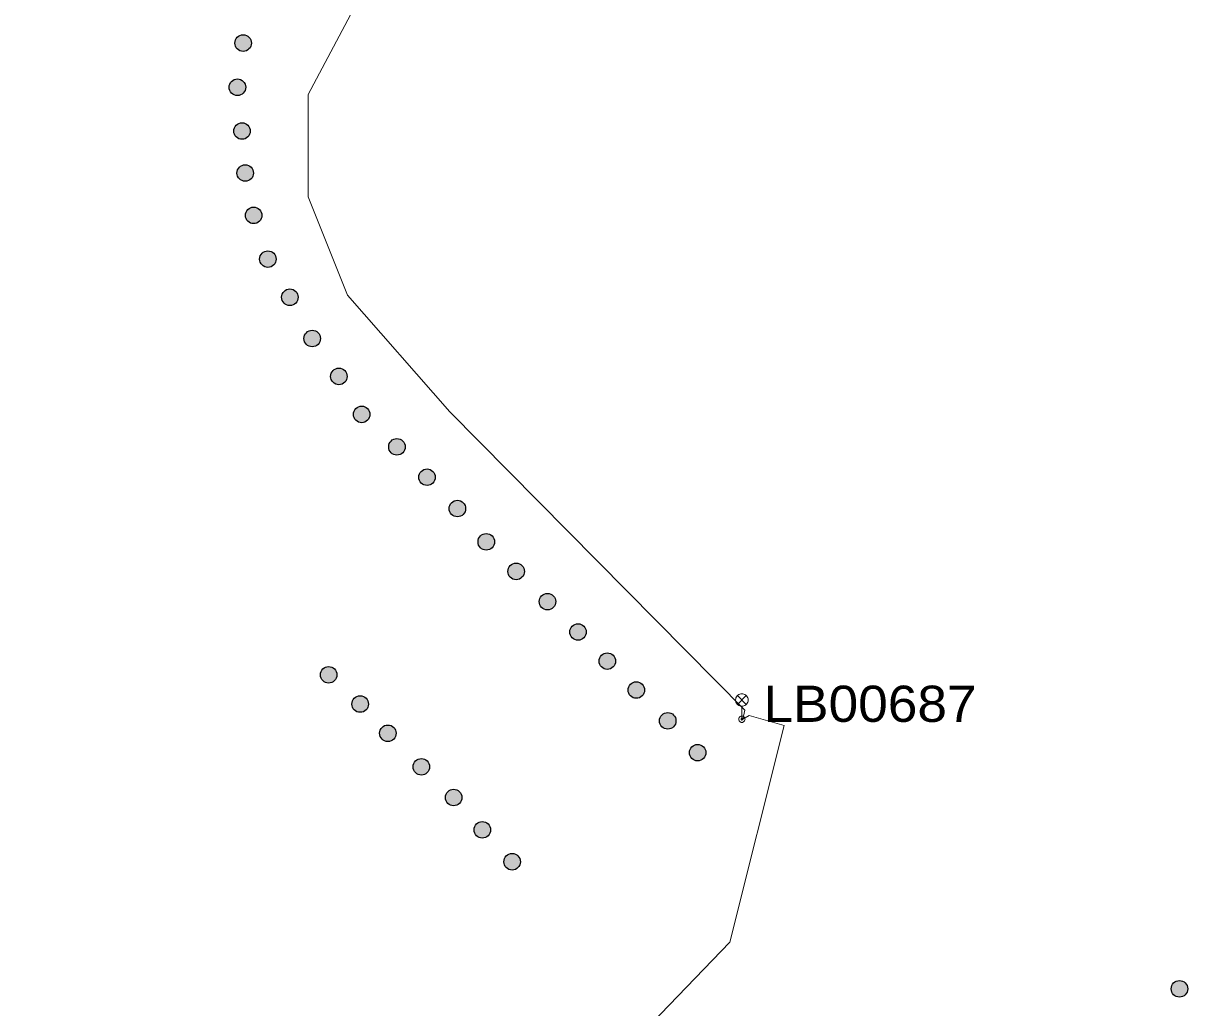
# Model space of a CAD drawing. Extents: x -688049 to -687261, y -973611 to -973038.
# Drawn here: x -687678.7 to -687609, y -973383.4 to -973324.5 of the extents above; entities that cross this region are included whole.
import ezdxf

# ---------------------------------------------------------------- set-up
doc = ezdxf.new("R2010")
doc.units = 0
doc.header["$LTSCALE"] = 0.87
doc.layers.add('1', color=7, linetype='Continuous', lineweight=13)

msp = doc.modelspace()

# ---------------------------------------------------------------- hatches: boundary and pattern name
at = {"layer": '1'}
for points in [[(-687665.392, -973326.145, 1), (-687665.691, -973325.201, 1)], [(-687665.735, -973328.789, 1), (-687666.034, -973327.845, 1)], [(-687665.46, -973331.41, 1), (-687665.759, -973330.466, 1)], [(-687665.267, -973333.924, 1), (-687665.566, -973332.979, 1)], [(-687664.763, -973336.457, 1), (-687665.062, -973335.513, 1)], [(-687663.91, -973339.074, 1), (-687664.209, -973338.13, 1)], [(-687662.593, -973341.358, 1), (-687662.892, -973340.414, 1)], [(-687661.255, -973343.827, 1), (-687661.553, -973342.883, 1)], [(-687659.656, -973346.096, 1), (-687659.955, -973345.152, 1)], [(-687658.292, -973348.37, 1), (-687658.591, -973347.426, 1)], [(-687656.18, -973350.311, 1), (-687656.478, -973349.367, 1)], [(-687654.379, -973352.128, 1), (-687654.678, -973351.184, 1)], [(-687652.558, -973354.004, 1), (-687652.857, -973353.059, 1)], [(-687650.829, -973355.995, 1), (-687651.128, -973355.051, 1)], [(-687649.04, -973357.767, 1), (-687649.338, -973356.823, 1)], [(-687647.162, -973359.575, 1), (-687647.461, -973358.631, 1)], [(-687645.333, -973361.392, 1), (-687645.632, -973360.448, 1)], [(-687643.58, -973363.135, 1), (-687643.878, -973362.191, 1)], [(-687660.271, -973363.955, 1), (-687660.57, -973363.011, 1)], [(-687641.841, -973364.867, 1), (-687642.14, -973363.923, 1)], [(-687658.383, -973365.705, 1), (-687658.682, -973364.761, 1)], [(-687639.961, -973366.71, 1), (-687640.26, -973365.766, 1)], [(-687656.723, -973367.454, 1), (-687657.022, -973366.51, 1)], [(-687638.17, -973368.613, 1), (-687638.469, -973367.669, 1)], [(-687654.717, -973369.461, 1), (-687655.016, -973368.517, 1)], [(-687652.784, -973371.299, 1), (-687653.083, -973370.355, 1)], [(-687651.068, -973373.233, 1), (-687651.367, -973372.289, 1)], [(-687649.28, -973375.143, 1), (-687649.578, -973374.199, 1)], [(-687609.311, -973382.749, 1), (-687609.609, -973381.805, 1)]]:
    msp.add_hatch(color=256, dxfattribs=at).paths.add_polyline_path(points)

# ---------------------------------------------------------------- linework, layer by layer
for p, q in [((-687635.935, -973364.725), (-687635.405, -973365.255)), ((-687635.935, -973365.255), (-687635.405, -973364.725)), ((-687635.67, -973366.14), (-687635.67, -973365.365))]:
    msp.add_line(p, q, dxfattribs=at)
for points in [[(-687678.71, -973323.61), (-687678.206, -973323.669), (-687658.771, -973323.345), (-687661.643, -973328.751), (-687661.643, -973334.873), (-687659.29, -973340.758), (-687653.159, -973347.738), (-687635.491, -973365.599), (-687635.62, -973366.14)], [(-687635.62, -973366.14), (-687635.225, -973365.919), (-687633.134, -973366.526), (-687636.395, -973379.478), (-687647.285, -973390.792), (-687642.829, -973395.545), (-687642.829, -973396.299), (-687642.074, -973396.299), (-687632.804, -973405.662), (-687632.954, -973409.811), (-687635.757, -973411.904), (-687636.24, -973411.98)]]:
    msp.add_lwpolyline(points, dxfattribs=at)
for points in [[(-687635.295, -973364.99), (-687635.301, -973364.925), (-687635.318, -973364.862), (-687635.345, -973364.802), (-687635.383, -973364.749), (-687635.429, -973364.703), (-687635.482, -973364.665), (-687635.542, -973364.638), (-687635.605, -973364.621), (-687635.67, -973364.615), (-687635.735, -973364.621), (-687635.798, -973364.638), (-687635.858, -973364.665), (-687635.911, -973364.703), (-687635.957, -973364.749), (-687635.995, -973364.802), (-687636.022, -973364.862), (-687636.039, -973364.925), (-687636.045, -973364.99), (-687636.039, -973365.055), (-687636.022, -973365.118), (-687635.995, -973365.178), (-687635.957, -973365.231), (-687635.911, -973365.277), (-687635.858, -973365.315), (-687635.798, -973365.342), (-687635.735, -973365.359), (-687635.67, -973365.365), (-687635.605, -973365.359), (-687635.542, -973365.342), (-687635.482, -973365.315), (-687635.429, -973365.277), (-687635.383, -973365.231), (-687635.345, -973365.178), (-687635.318, -973365.118), (-687635.301, -973365.055)], [(-687635.48, -973366.14), (-687635.483, -973366.107), (-687635.491, -973366.075), (-687635.505, -973366.045), (-687635.524, -973366.018), (-687635.548, -973365.994), (-687635.575, -973365.975), (-687635.605, -973365.961), (-687635.637, -973365.953), (-687635.67, -973365.95), (-687635.703, -973365.953), (-687635.735, -973365.961), (-687635.765, -973365.975), (-687635.792, -973365.994), (-687635.816, -973366.018), (-687635.835, -973366.045), (-687635.849, -973366.075), (-687635.857, -973366.107), (-687635.86, -973366.14), (-687635.857, -973366.173), (-687635.849, -973366.205), (-687635.835, -973366.235), (-687635.816, -973366.262), (-687635.792, -973366.286), (-687635.765, -973366.305), (-687635.735, -973366.319), (-687635.703, -973366.327), (-687635.67, -973366.33), (-687635.637, -973366.327), (-687635.605, -973366.319), (-687635.575, -973366.305), (-687635.548, -973366.286), (-687635.524, -973366.262), (-687635.505, -973366.235), (-687635.491, -973366.205), (-687635.483, -973366.173)], [(-687635.62, -973366.14), (-687635.621, -973366.131), (-687635.623, -973366.123), (-687635.627, -973366.115), (-687635.632, -973366.108), (-687635.638, -973366.102), (-687635.645, -973366.097), (-687635.653, -973366.093), (-687635.661, -973366.091), (-687635.67, -973366.09), (-687635.679, -973366.091), (-687635.687, -973366.093), (-687635.695, -973366.097), (-687635.702, -973366.102), (-687635.708, -973366.108), (-687635.713, -973366.115), (-687635.717, -973366.123), (-687635.719, -973366.131), (-687635.72, -973366.14), (-687635.719, -973366.149), (-687635.717, -973366.157), (-687635.713, -973366.165), (-687635.708, -973366.172), (-687635.702, -973366.178), (-687635.695, -973366.183), (-687635.687, -973366.187), (-687635.679, -973366.189), (-687635.67, -973366.19), (-687635.661, -973366.189), (-687635.653, -973366.187), (-687635.645, -973366.183), (-687635.638, -973366.178), (-687635.632, -973366.172), (-687635.627, -973366.165), (-687635.623, -973366.157), (-687635.621, -973366.149)]]:
    msp.add_lwpolyline(points, close=True, dxfattribs=at)
at = {"layer": '1', "lineweight": 25}
for centre in [(-687665.541, -973325.673), (-687665.884, -973328.317), (-687665.609, -973330.938), (-687665.417, -973333.451), (-687664.912, -973335.985), (-687664.059, -973338.602), (-687662.742, -973340.886), (-687661.404, -973343.355), (-687659.806, -973345.624), (-687658.442, -973347.898), (-687656.329, -973349.839), (-687654.528, -973351.656), (-687652.708, -973353.532), (-687650.979, -973355.523), (-687649.189, -973357.295), (-687647.312, -973359.103), (-687645.483, -973360.92), (-687643.729, -973362.663), (-687660.421, -973363.483), (-687641.991, -973364.395), (-687658.532, -973365.233), (-687640.11, -973366.238), (-687656.872, -973366.982), (-687638.319, -973368.141), (-687654.866, -973368.989), (-687652.933, -973370.827), (-687651.217, -973372.761), (-687649.429, -973374.671), (-687609.46, -973382.277)]:
    msp.add_circle(centre, 0.495, dxfattribs=at)

# ---------------------------------------------------------------- texts
at = {"layer": '1', "width": 1.1}
msp.add_text('LB00687', height=2.167, dxfattribs=at).set_placement((-687634.374, -973366.3))

doc.saveas('drawing.dxf')
